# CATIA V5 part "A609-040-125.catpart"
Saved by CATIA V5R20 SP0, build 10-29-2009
Part number: A609-040-125
Source: Unknown
Property "ARTICLENO": "A609-040-125"
Property "B": "30.000"
Property "BOMINFO": "A609-040-125"
Property "CODE": "A609-040-125"
Property "D": "20.000"
Property "D1": "13.500"
Property "FORM": "A"
Property "L": "125.000"
Property "L1": "25.000"
Property "L2": "75.000"
Property "LINA": "A609-040-125"
Property "NB": "A609-040-125"
Property "NBSYN": "$CODE."
Property "NN": "A609"
Property "NT": "VDI 3357 E-Type Wear Plates, self-lubricating"
Property "S": "40.000"
Property "SUPPLIER": "CF"
Property "T": "13.000"
Property "W": "60.000"
Bounding box of the stored display mesh (mm): x 0 to 125, y 0 to 40, z 0 to 60
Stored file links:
  C:\Users\Utente\Desktop\3D files A609\A609-040-125.catpart
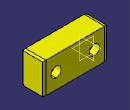
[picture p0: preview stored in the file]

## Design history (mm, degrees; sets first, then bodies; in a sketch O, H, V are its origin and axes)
Body1 "Geometry.1" (main body)
  Solid1 "A609-040-125.catpart": solid without history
